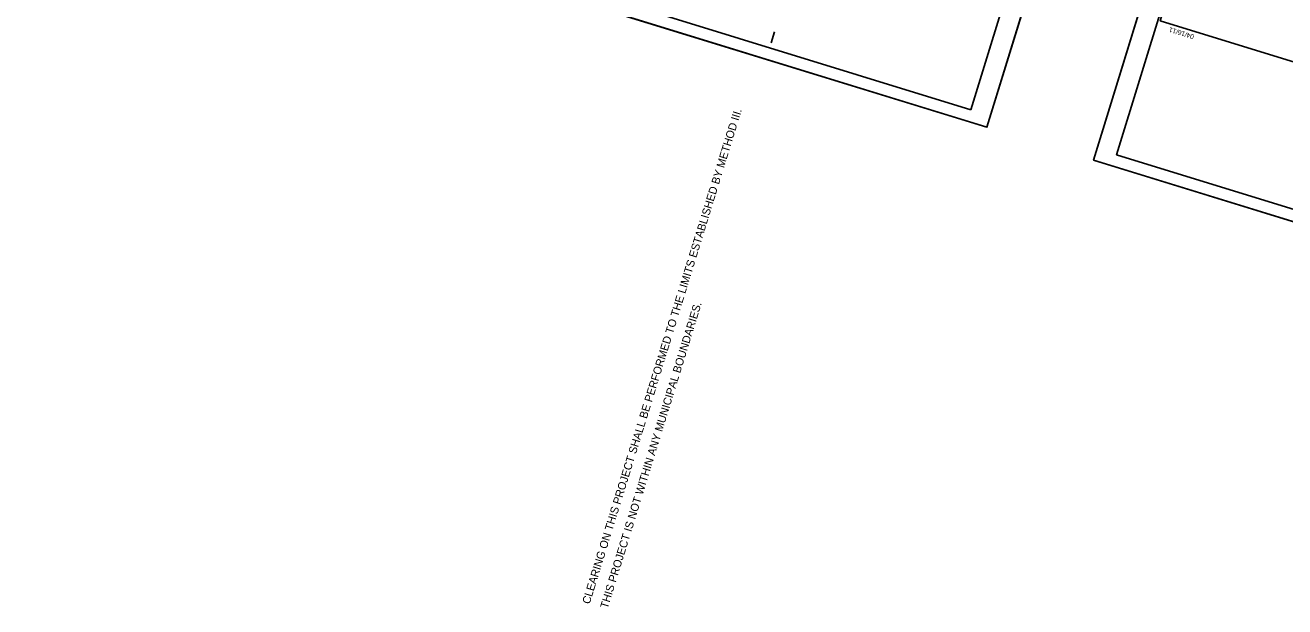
# Model space of a CAD drawing. Extents: x 1347947 to 1350662, y 1027710 to 1030532.
# Drawn here: x 1347947 to 1349324, y 1027710 to 1028346 of the extents above; entities that cross this region are included whole.
import ezdxf

# ---------------------------------------------------------------- set-up
doc = ezdxf.new("R2010")
doc.units = 0
for name, color, linetype in [('Sheet Cutting Line CELL', 7, 'Continuous'), ('Sheet Data Field CELL', 7, 'Continuous'), ('Sheet Plot Border Inside CELL', 7, 'Continuous'), ('Sheet Plot Border Outside CELL', 7, 'Continuous'), ('Sheet Symbology CELL', 7, 'Continuous'), ('Sheet Title CELL', 7, 'Continuous')]:
    doc.layers.add(name, color=color, linetype=linetype)

msp = doc.modelspace()

# ---------------------------------------------------------------- linework, layer by layer
at = {"layer": 'Sheet Cutting Line CELL'}
for p, q in [((1348998.1, 1028234.2), (1349493.8, 1029843.6)), ((1347946.9, 1028558), (1348998.1, 1028234.2))]:
    msp.add_line(p, q, dxfattribs=at)
at = {"layer": 'Sheet Plot Border Inside CELL'}
msp.add_lwpolyline([(1348980.5, 1028253.2), (1349471, 1029845.9), (1348462.6, 1030156.5), (1347972.2, 1028563.8)], close=True, dxfattribs=at)
at = {"layer": 'Sheet Plot Border Outside CELL'}
msp.add_lwpolyline([(1348442.5, 1030167.4), (1347946.9, 1028558), (1348998.1, 1028234.2), (1349493.8, 1029843.6)], close=True, dxfattribs=at)
at = {"layer": 'Sheet Symbology CELL'}
for p, q in [((1349610.3, 1029807.7), (1349114.7, 1028198.3)), ((1349114.7, 1028198.3), (1350166, 1027874.5))]:
    msp.add_line(p, q, dxfattribs=at)
for points in [[(1350166, 1027874.5), (1350661.6, 1029484), (1349610.3, 1029807.7), (1349114.7, 1028198.3)], [(1350148.3, 1027893.6), (1350638.8, 1029486.3), (1349630.5, 1029796.8), (1349140, 1028204.1)], [(1349629.2, 1029784.1), (1349187.7, 1028350.5), (1350190.3, 1028041.8), (1350631.7, 1029475.4)]]:
    msp.add_lwpolyline(points, close=True, dxfattribs=at)
at = {"layer": 'Sheet Title CELL'}
msp.add_line((1348762.3, 1028326.2), (1348766, 1028338.2), dxfattribs=at)
msp.add_line((1348762.3, 1028326.2), (1348766, 1028338.2), dxfattribs=at)

# ---------------------------------------------------------------- texts
at = {"layer": 'Sheet Data Field CELL'}
for s, p in [('CLEARING ON THIS PROJECT SHALL BE PERFORMED TO THE LIMITS ESTABLISHED BY METHOD III.', (1348563.9, 1027712.5)), ('THIS PROJECT IS NOT WITHIN ANY MUNICIPAL BOUNDARIES.', (1348583.6, 1027707.6))]:
    msp.add_text(s, height=8.75, rotation=72.8834, dxfattribs=at).set_placement(p)
at = {"layer": 'Sheet Symbology CELL'}
msp.add_text('04/16/11', height=5.25, rotation=162.8834, dxfattribs=at).set_placement((1349225.1, 1028335.2))

doc.saveas('drawing.dxf')
